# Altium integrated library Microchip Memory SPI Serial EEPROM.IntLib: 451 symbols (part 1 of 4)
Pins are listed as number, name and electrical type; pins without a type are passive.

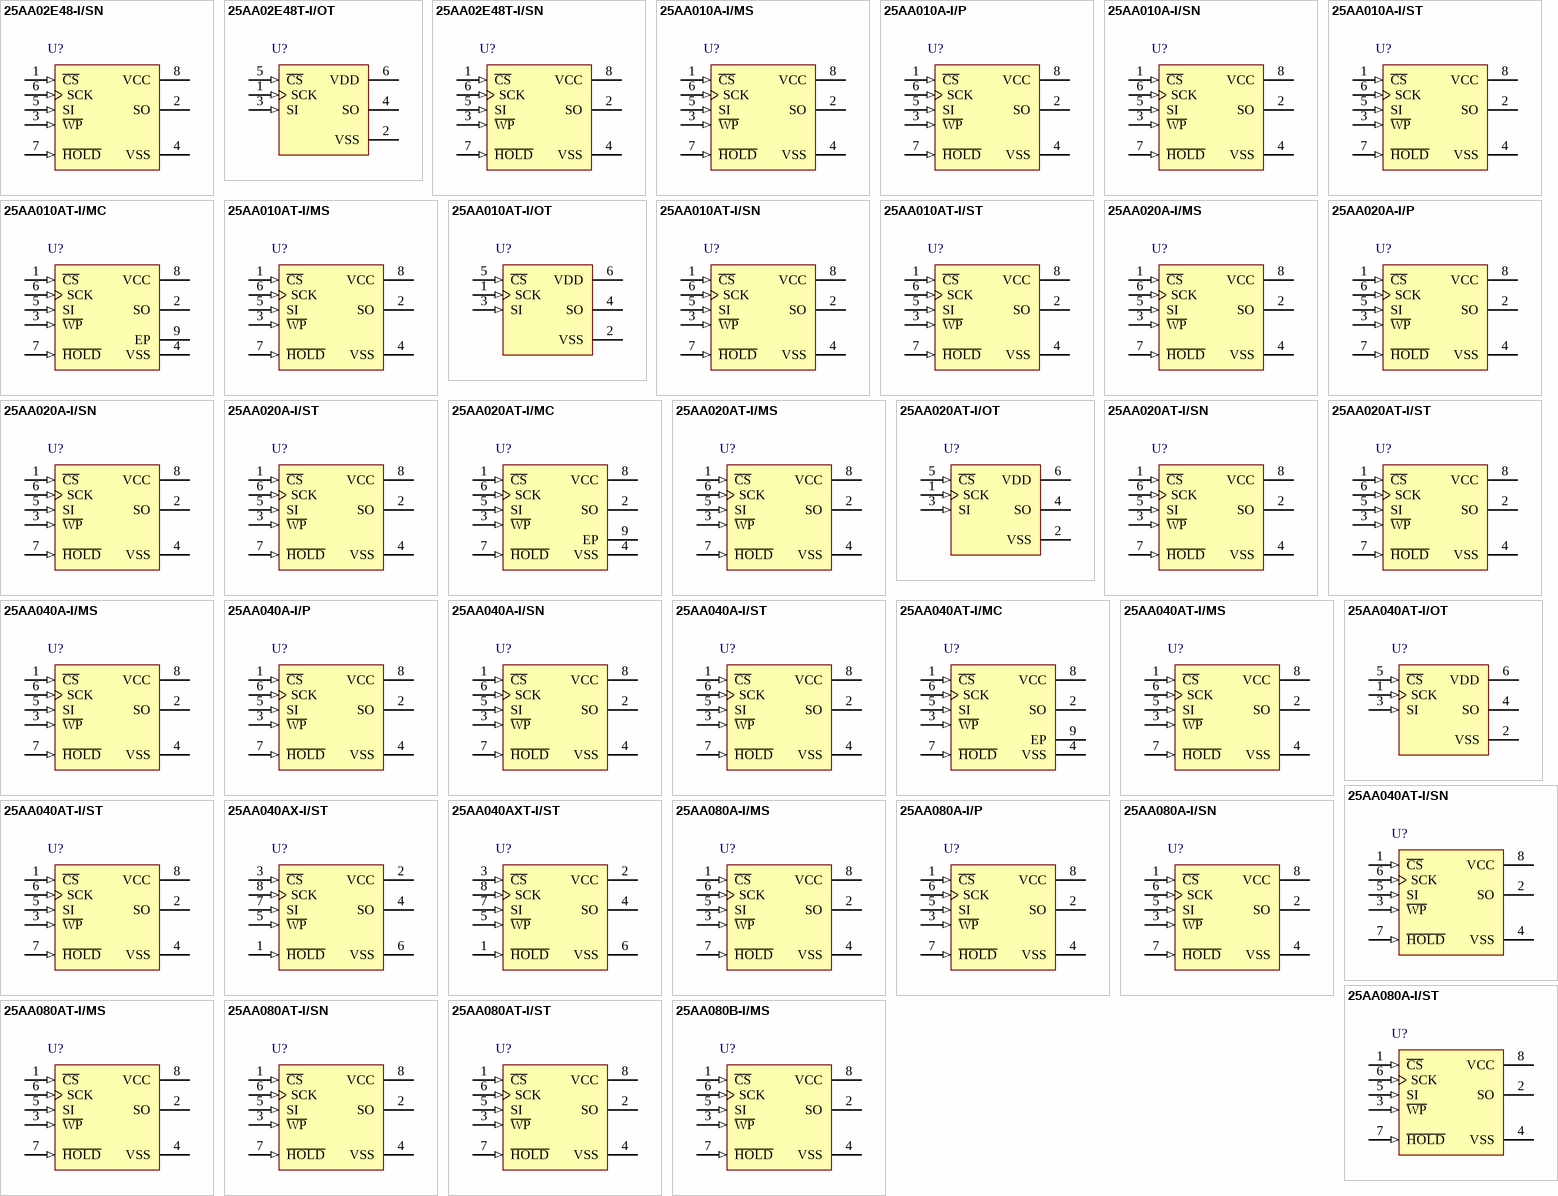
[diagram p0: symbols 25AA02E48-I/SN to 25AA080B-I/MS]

## 25AA02E48-I/SN
designator U?
2K SPI Bus Serial EEPROM with EUI-48 Node Identity, 8-Pin SOIC, Industrial Temperature
footprint SOIC-SN8_N (SOIC, 8-Leads, Body 4.9x3.8mm, Pitch 1.27mm, IPC Medium Density)
footprint SOIC-SN8_L (SOIC, 8-Leads, Body 4.9x3.8mm, Pitch 1.27mm, IPC High Density)
footprint SOIC-SN8_M (SOIC, 8-Leads, Body 4.9x3.8mm, Pitch 1.27mm, IPC Low Density)
pins: 1 ~{CS} (in), 2 SO (hiz), 3 ~{WP} (in), 4 VSS (power), 5 SI (in), 6 SCK (in), 7 ~{HOLD} (in), 8 VCC (power)

## 25AA02E48T-I/OT
designator U?
2K SPI Bus Serial EEPROM with EUI-48 Node Identity, 6-Pin SOT-23, Industrial Temperature, Tape and Reel
footprint SOT-23-OT6_N (SOT23, 6-Leads, Body 2.9x1.6mm, Pitch 0.95mm, Lead Span 2.7mm, IPC Medium Density)
footprint SOT-23-OT6_L (SOT23, 6-Leads, Body 2.9x1.6mm, Pitch 0.95mm, Lead Span 2.7mm, IPC High Density)
footprint SOT-23-OT6_M (SOT23, 6-Leads, Body 2.9x1.6mm, Pitch 0.95mm, Lead Span 2.7mm, IPC Low Density)
pins: 1 SCK (in), 2 VSS (power), 3 SI (in), 4 SO (hiz), 5 ~{CS} (in), 6 VDD (power)

## 25AA02E48T-I/SN
designator U?
2K SPI Bus Serial EEPROM with EUI-48 Node Identity, 8-Pin SOIC, Industrial Temperature, Tape and Reel
footprint SOIC-SN8_N (SOIC, 8-Leads, Body 4.9x3.8mm, Pitch 1.27mm, IPC Medium Density)
footprint SOIC-SN8_L (SOIC, 8-Leads, Body 4.9x3.8mm, Pitch 1.27mm, IPC High Density)
footprint SOIC-SN8_M (SOIC, 8-Leads, Body 4.9x3.8mm, Pitch 1.27mm, IPC Low Density)
pins: 1 ~{CS} (in), 2 SO (hiz), 3 ~{WP} (in), 4 VSS (power), 5 SI (in), 6 SCK (in), 7 ~{HOLD} (in), 8 VCC (power)

## 25AA010A-I/MS
designator U?
1K SPI Bus Serial EEPROM, 8-Pin MSOP, Industrial Temperature
footprint MSOP-MS8_N (TSOP, 8-Leads, Body 3x3mm, Pitch 0.65mm, IPC Medium Density)
footprint MSOP-MS8_L (TSOP, 8-Leads, Body 3x3mm, Pitch 0.65mm, IPC High Density)
footprint MSOP-MS8_M (TSOP, 8-Leads, Body 3x3mm, Pitch 0.65mm, IPC Low Density)
pins: 1 ~{CS} (in), 2 SO (hiz), 3 ~{WP} (in), 4 VSS (power), 5 SI (in), 6 SCK (in), 7 ~{HOLD} (in), 8 VCC (power)

## 25AA010A-I/P
designator U?
1K SPI Bus Serial EEPROM, 8-Pin PDIP, Industrial Temperature
footprint PDIP300-P8 (DIP, 8-Leads, Row Spacing 7.62mm, Pitch 2.54mm, Body 9.5x6.6mm)
pins: 1 ~{CS} (in), 2 SO (hiz), 3 ~{WP} (in), 4 VSS (power), 5 SI (in), 6 SCK (in), 7 ~{HOLD} (in), 8 VCC (power)

## 25AA010A-I/SN
designator U?
1K SPI Bus Serial EEPROM, 8-Pin SOIC, Industrial Temperature
footprint SOIC-SN8_N (SOIC, 8-Leads, Body 4.9x3.8mm, Pitch 1.27mm, IPC Medium Density)
footprint SOIC-SN8_L (SOIC, 8-Leads, Body 4.9x3.8mm, Pitch 1.27mm, IPC High Density)
footprint SOIC-SN8_M (SOIC, 8-Leads, Body 4.9x3.8mm, Pitch 1.27mm, IPC Low Density)
pins: 1 ~{CS} (in), 2 SO (hiz), 3 ~{WP} (in), 4 VSS (power), 5 SI (in), 6 SCK (in), 7 ~{HOLD} (in), 8 VCC (power)

## 25AA010A-I/ST
designator U?
1K SPI Bus Serial EEPROM, 8-Pin TSSOP, Industrial Temperature
footprint TSSOP-ST8_N (TSOP, 8-Leads, Body 3x4.4mm, Pitch 0.65mm, IPC Medium Density)
footprint TSSOP-ST8_L (TSOP, 8-Leads, Body 3x4.4mm, Pitch 0.65mm, IPC High Density)
footprint TSSOP-ST8_M (TSOP, 8-Leads, Body 3x4.4mm, Pitch 0.65mm, IPC Low Density)
pins: 1 ~{CS} (in), 2 SO (hiz), 3 ~{WP} (in), 4 VSS (power), 5 SI (in), 6 SCK (in), 7 ~{HOLD} (in), 8 VCC (power)

## 25AA010AT-I/MC
designator U?
1K SPI Bus Serial EEPROM, 8-Pin DFN, Industrial Temperature, Tape and Reel
footprint DFN-MC8 (SON, 8-Leads, Body 2x3mm, Pitch 0.5mm, Microchip Recommended)
pins: 1 ~{CS} (in), 2 SO (hiz), 3 ~{WP} (in), 4 VSS (power), 5 SI (in), 6 SCK (in), 7 ~{HOLD} (in), 8 VCC (power), 9 EP

## 25AA010AT-I/MS
designator U?
1K SPI Bus Serial EEPROM, 8-Pin MSOP, Industrial Temperature, Tape and Reel
footprint MSOP-MS8_N (TSOP, 8-Leads, Body 3x3mm, Pitch 0.65mm, IPC Medium Density)
footprint MSOP-MS8_L (TSOP, 8-Leads, Body 3x3mm, Pitch 0.65mm, IPC High Density)
footprint MSOP-MS8_M (TSOP, 8-Leads, Body 3x3mm, Pitch 0.65mm, IPC Low Density)
pins: 1 ~{CS} (in), 2 SO (hiz), 3 ~{WP} (in), 4 VSS (power), 5 SI (in), 6 SCK (in), 7 ~{HOLD} (in), 8 VCC (power)

## 25AA010AT-I/OT
designator U?
1K SPI Bus Serial EEPROM, 6-Pin SOT-23, Industrial Temperature, Tape and Reel
footprint SOT-23-OT6_N (SOT23, 6-Leads, Body 2.9x1.6mm, Pitch 0.95mm, Lead Span 2.7mm, IPC Medium Density)
footprint SOT-23-OT6_L (SOT23, 6-Leads, Body 2.9x1.6mm, Pitch 0.95mm, Lead Span 2.7mm, IPC High Density)
footprint SOT-23-OT6_M (SOT23, 6-Leads, Body 2.9x1.6mm, Pitch 0.95mm, Lead Span 2.7mm, IPC Low Density)
pins: 1 SCK (in), 2 VSS (power), 3 SI (in), 4 SO (hiz), 5 ~{CS} (in), 6 VDD (power)

## 25AA010AT-I/SN
designator U?
1K SPI Bus Serial EEPROM, 8-Pin SOIC, Industrial Temperature, Tape and Reel
footprint SOIC-SN8_N (SOIC, 8-Leads, Body 4.9x3.8mm, Pitch 1.27mm, IPC Medium Density)
footprint SOIC-SN8_L (SOIC, 8-Leads, Body 4.9x3.8mm, Pitch 1.27mm, IPC High Density)
footprint SOIC-SN8_M (SOIC, 8-Leads, Body 4.9x3.8mm, Pitch 1.27mm, IPC Low Density)
pins: 1 ~{CS} (in), 2 SO (hiz), 3 ~{WP} (in), 4 VSS (power), 5 SI (in), 6 SCK (in), 7 ~{HOLD} (in), 8 VCC (power)

## 25AA010AT-I/ST
designator U?
1K SPI Bus Serial EEPROM, 8-Pin TSSOP, Industrial Temperature, Tape and Reel
footprint TSSOP-ST8_N (TSOP, 8-Leads, Body 3x4.4mm, Pitch 0.65mm, IPC Medium Density)
footprint TSSOP-ST8_L (TSOP, 8-Leads, Body 3x4.4mm, Pitch 0.65mm, IPC High Density)
footprint TSSOP-ST8_M (TSOP, 8-Leads, Body 3x4.4mm, Pitch 0.65mm, IPC Low Density)
pins: 1 ~{CS} (in), 2 SO (hiz), 3 ~{WP} (in), 4 VSS (power), 5 SI (in), 6 SCK (in), 7 ~{HOLD} (in), 8 VCC (power)

## 25AA020A-I/MS
designator U?
2K SPI Bus Serial EEPROM, 8-Pin MSOP, Industrial Temperature
footprint MSOP-MS8_N (TSOP, 8-Leads, Body 3x3mm, Pitch 0.65mm, IPC Medium Density)
footprint MSOP-MS8_L (TSOP, 8-Leads, Body 3x3mm, Pitch 0.65mm, IPC High Density)
footprint MSOP-MS8_M (TSOP, 8-Leads, Body 3x3mm, Pitch 0.65mm, IPC Low Density)
pins: 1 ~{CS} (in), 2 SO (hiz), 3 ~{WP} (in), 4 VSS (power), 5 SI (in), 6 SCK (in), 7 ~{HOLD} (in), 8 VCC (power)

## 25AA020A-I/P
designator U?
2K SPI Bus Serial EEPROM, 8-Pin PDIP, Industrial Temperature
footprint PDIP300-P8 (DIP, 8-Leads, Row Spacing 7.62mm, Pitch 2.54mm, Body 9.5x6.6mm)
pins: 1 ~{CS} (in), 2 SO (hiz), 3 ~{WP} (in), 4 VSS (power), 5 SI (in), 6 SCK (in), 7 ~{HOLD} (in), 8 VCC (power)

## 25AA020A-I/SN
designator U?
2K SPI Bus Serial EEPROM, 8-Pin SOIC, Industrial Temperature
footprint SOIC-SN8_N (SOIC, 8-Leads, Body 4.9x3.8mm, Pitch 1.27mm, IPC Medium Density)
footprint SOIC-SN8_L (SOIC, 8-Leads, Body 4.9x3.8mm, Pitch 1.27mm, IPC High Density)
footprint SOIC-SN8_M (SOIC, 8-Leads, Body 4.9x3.8mm, Pitch 1.27mm, IPC Low Density)
pins: 1 ~{CS} (in), 2 SO (hiz), 3 ~{WP} (in), 4 VSS (power), 5 SI (in), 6 SCK (in), 7 ~{HOLD} (in), 8 VCC (power)

## 25AA020A-I/ST
designator U?
2K SPI Bus Serial EEPROM, 8-Pin TSSOP, Industrial Temperature
footprint TSSOP-ST8_N (TSOP, 8-Leads, Body 3x4.4mm, Pitch 0.65mm, IPC Medium Density)
footprint TSSOP-ST8_L (TSOP, 8-Leads, Body 3x4.4mm, Pitch 0.65mm, IPC High Density)
footprint TSSOP-ST8_M (TSOP, 8-Leads, Body 3x4.4mm, Pitch 0.65mm, IPC Low Density)
pins: 1 ~{CS} (in), 2 SO (hiz), 3 ~{WP} (in), 4 VSS (power), 5 SI (in), 6 SCK (in), 7 ~{HOLD} (in), 8 VCC (power)

## 25AA020AT-I/MC
designator U?
2K SPI Bus Serial EEPROM, 8-Pin DFN, Industrial Temperature, Tape and Reel
footprint DFN-MC8 (SON, 8-Leads, Body 2x3mm, Pitch 0.5mm, Microchip Recommended)
pins: 1 ~{CS} (in), 2 SO (hiz), 3 ~{WP} (in), 4 VSS (power), 5 SI (in), 6 SCK (in), 7 ~{HOLD} (in), 8 VCC (power), 9 EP

## 25AA020AT-I/MS
designator U?
2K SPI Bus Serial EEPROM, 8-Pin MSOP, Industrial Temperature, Tape and Reel
footprint MSOP-MS8_N (TSOP, 8-Leads, Body 3x3mm, Pitch 0.65mm, IPC Medium Density)
footprint MSOP-MS8_L (TSOP, 8-Leads, Body 3x3mm, Pitch 0.65mm, IPC High Density)
footprint MSOP-MS8_M (TSOP, 8-Leads, Body 3x3mm, Pitch 0.65mm, IPC Low Density)
pins: 1 ~{CS} (in), 2 SO (hiz), 3 ~{WP} (in), 4 VSS (power), 5 SI (in), 6 SCK (in), 7 ~{HOLD} (in), 8 VCC (power)

## 25AA020AT-I/OT
designator U?
2K SPI Bus Serial EEPROM, 6-Pin SOT-23, Industrial Temperature, Tape and Reel
footprint SOT-23-OT6_N (SOT23, 6-Leads, Body 2.9x1.6mm, Pitch 0.95mm, Lead Span 2.7mm, IPC Medium Density)
footprint SOT-23-OT6_L (SOT23, 6-Leads, Body 2.9x1.6mm, Pitch 0.95mm, Lead Span 2.7mm, IPC High Density)
footprint SOT-23-OT6_M (SOT23, 6-Leads, Body 2.9x1.6mm, Pitch 0.95mm, Lead Span 2.7mm, IPC Low Density)
pins: 1 SCK (in), 2 VSS (power), 3 SI (in), 4 SO (hiz), 5 ~{CS} (in), 6 VDD (power)

## 25AA020AT-I/SN
designator U?
2K SPI Bus Serial EEPROM, 8-Pin SOIC, Industrial Temperature, Tape and Reel
footprint SOIC-SN8_N (SOIC, 8-Leads, Body 4.9x3.8mm, Pitch 1.27mm, IPC Medium Density)
footprint SOIC-SN8_L (SOIC, 8-Leads, Body 4.9x3.8mm, Pitch 1.27mm, IPC High Density)
footprint SOIC-SN8_M (SOIC, 8-Leads, Body 4.9x3.8mm, Pitch 1.27mm, IPC Low Density)
pins: 1 ~{CS} (in), 2 SO (hiz), 3 ~{WP} (in), 4 VSS (power), 5 SI (in), 6 SCK (in), 7 ~{HOLD} (in), 8 VCC (power)

## 25AA020AT-I/ST
designator U?
2K SPI Bus Serial EEPROM, 8-Pin TSSOP, Industrial Temperature, Tape and Reel
footprint TSSOP-ST8_N (TSOP, 8-Leads, Body 3x4.4mm, Pitch 0.65mm, IPC Medium Density)
footprint TSSOP-ST8_L (TSOP, 8-Leads, Body 3x4.4mm, Pitch 0.65mm, IPC High Density)
footprint TSSOP-ST8_M (TSOP, 8-Leads, Body 3x4.4mm, Pitch 0.65mm, IPC Low Density)
pins: 1 ~{CS} (in), 2 SO (hiz), 3 ~{WP} (in), 4 VSS (power), 5 SI (in), 6 SCK (in), 7 ~{HOLD} (in), 8 VCC (power)

## 25AA040A-I/MS
designator U?
4K SPI Bus Serial EEPROM, 8-Pin MSOP, Industrial Temperature
footprint MSOP-MS8_N (TSOP, 8-Leads, Body 3x3mm, Pitch 0.65mm, IPC Medium Density)
footprint MSOP-MS8_L (TSOP, 8-Leads, Body 3x3mm, Pitch 0.65mm, IPC High Density)
footprint MSOP-MS8_M (TSOP, 8-Leads, Body 3x3mm, Pitch 0.65mm, IPC Low Density)
pins: 1 ~{CS} (in), 2 SO (hiz), 3 ~{WP} (in), 4 VSS (power), 5 SI (in), 6 SCK (in), 7 ~{HOLD} (in), 8 VCC (power)

## 25AA040A-I/P
designator U?
4K SPI Bus Serial EEPROM, 8-Pin PDIP, Industrial Temperature
footprint PDIP300-P8 (DIP, 8-Leads, Row Spacing 7.62mm, Pitch 2.54mm, Body 9.5x6.6mm)
pins: 1 ~{CS} (in), 2 SO (hiz), 3 ~{WP} (in), 4 VSS (power), 5 SI (in), 6 SCK (in), 7 ~{HOLD} (in), 8 VCC (power)

## 25AA040A-I/SN
designator U?
4K SPI Bus Serial EEPROM, 8-Pin SOIC, Industrial Temperature
footprint SOIC-SN8_N (SOIC, 8-Leads, Body 4.9x3.8mm, Pitch 1.27mm, IPC Medium Density)
footprint SOIC-SN8_L (SOIC, 8-Leads, Body 4.9x3.8mm, Pitch 1.27mm, IPC High Density)
footprint SOIC-SN8_M (SOIC, 8-Leads, Body 4.9x3.8mm, Pitch 1.27mm, IPC Low Density)
pins: 1 ~{CS} (in), 2 SO (hiz), 3 ~{WP} (in), 4 VSS (power), 5 SI (in), 6 SCK (in), 7 ~{HOLD} (in), 8 VCC (power)

## 25AA040A-I/ST
designator U?
4K SPI Bus Serial EEPROM, 8-Pin TSSOP, Industrial Temperature
footprint TSSOP-ST8_N (TSOP, 8-Leads, Body 3x4.4mm, Pitch 0.65mm, IPC Medium Density)
footprint TSSOP-ST8_L (TSOP, 8-Leads, Body 3x4.4mm, Pitch 0.65mm, IPC High Density)
footprint TSSOP-ST8_M (TSOP, 8-Leads, Body 3x4.4mm, Pitch 0.65mm, IPC Low Density)
pins: 1 ~{CS} (in), 2 SO (hiz), 3 ~{WP} (in), 4 VSS (power), 5 SI (in), 6 SCK (in), 7 ~{HOLD} (in), 8 VCC (power)

## 25AA040AT-I/MC
designator U?
4K SPI Bus Serial EEPROM, 8-Pin DFN, Industrial Temperature, Tape and Reel
footprint DFN-MC8 (SON, 8-Leads, Body 2x3mm, Pitch 0.5mm, Microchip Recommended)
pins: 1 ~{CS} (in), 2 SO (hiz), 3 ~{WP} (in), 4 VSS (power), 5 SI (in), 6 SCK (in), 7 ~{HOLD} (in), 8 VCC (power), 9 EP

## 25AA040AT-I/MS
designator U?
4K SPI Bus Serial EEPROM, 8-Pin MSOP, Industrial Temperature, Tape and Reel
footprint MSOP-MS8_N (TSOP, 8-Leads, Body 3x3mm, Pitch 0.65mm, IPC Medium Density)
footprint MSOP-MS8_L (TSOP, 8-Leads, Body 3x3mm, Pitch 0.65mm, IPC High Density)
footprint MSOP-MS8_M (TSOP, 8-Leads, Body 3x3mm, Pitch 0.65mm, IPC Low Density)
pins: 1 ~{CS} (in), 2 SO (hiz), 3 ~{WP} (in), 4 VSS (power), 5 SI (in), 6 SCK (in), 7 ~{HOLD} (in), 8 VCC (power)

## 25AA040AT-I/OT
designator U?
4K SPI Bus Serial EEPROM, 6-Pin SOT-23, Industrial Temperature, Tape and Reel
footprint SOT-23-OT6_N (SOT23, 6-Leads, Body 2.9x1.6mm, Pitch 0.95mm, Lead Span 2.7mm, IPC Medium Density)
footprint SOT-23-OT6_L (SOT23, 6-Leads, Body 2.9x1.6mm, Pitch 0.95mm, Lead Span 2.7mm, IPC High Density)
footprint SOT-23-OT6_M (SOT23, 6-Leads, Body 2.9x1.6mm, Pitch 0.95mm, Lead Span 2.7mm, IPC Low Density)
pins: 1 SCK (in), 2 VSS (power), 3 SI (in), 4 SO (hiz), 5 ~{CS} (in), 6 VDD (power)

## 25AA040AT-I/SN
designator U?
4K SPI Bus Serial EEPROM, 8-Pin SOIC, Industrial Temperature, Tape and Reel
footprint SOIC-SN8_N (SOIC, 8-Leads, Body 4.9x3.8mm, Pitch 1.27mm, IPC Medium Density)
footprint SOIC-SN8_L (SOIC, 8-Leads, Body 4.9x3.8mm, Pitch 1.27mm, IPC High Density)
footprint SOIC-SN8_M (SOIC, 8-Leads, Body 4.9x3.8mm, Pitch 1.27mm, IPC Low Density)
pins: 1 ~{CS} (in), 2 SO (hiz), 3 ~{WP} (in), 4 VSS (power), 5 SI (in), 6 SCK (in), 7 ~{HOLD} (in), 8 VCC (power)

## 25AA040AT-I/ST
designator U?
4K SPI Bus Serial EEPROM, 8-Pin TSSOP, Industrial Temperature, Tape and Reel
footprint TSSOP-ST8_N (TSOP, 8-Leads, Body 3x4.4mm, Pitch 0.65mm, IPC Medium Density)
footprint TSSOP-ST8_L (TSOP, 8-Leads, Body 3x4.4mm, Pitch 0.65mm, IPC High Density)
footprint TSSOP-ST8_M (TSOP, 8-Leads, Body 3x4.4mm, Pitch 0.65mm, IPC Low Density)
pins: 1 ~{CS} (in), 2 SO (hiz), 3 ~{WP} (in), 4 VSS (power), 5 SI (in), 6 SCK (in), 7 ~{HOLD} (in), 8 VCC (power)

## 25AA040AX-I/ST
designator U?
4K SPI Bus Serial EEPROM, 8-Pin TSSOP, Industrial Temperature
footprint TSSOP-ST8_N (TSOP, 8-Leads, Body 3x4.4mm, Pitch 0.65mm, IPC Medium Density)
footprint TSSOP-ST8_L (TSOP, 8-Leads, Body 3x4.4mm, Pitch 0.65mm, IPC High Density)
footprint TSSOP-ST8_M (TSOP, 8-Leads, Body 3x4.4mm, Pitch 0.65mm, IPC Low Density)
pins: 1 ~{HOLD} (in), 2 VCC (power), 3 ~{CS} (in), 4 SO (hiz), 5 ~{WP} (in), 6 VSS (power), 7 SI (in), 8 SCK (in)

## 25AA040AXT-I/ST
designator U?
4K SPI Bus Serial EEPROM, 8-Pin TSSOP, Industrial Temperature, Tape and Reel
footprint TSSOP-ST8_N (TSOP, 8-Leads, Body 3x4.4mm, Pitch 0.65mm, IPC Medium Density)
footprint TSSOP-ST8_L (TSOP, 8-Leads, Body 3x4.4mm, Pitch 0.65mm, IPC High Density)
footprint TSSOP-ST8_M (TSOP, 8-Leads, Body 3x4.4mm, Pitch 0.65mm, IPC Low Density)
pins: 1 ~{HOLD} (in), 2 VCC (power), 3 ~{CS} (in), 4 SO (hiz), 5 ~{WP} (in), 6 VSS (power), 7 SI (in), 8 SCK (in)

## 25AA080A-I/MS
designator U?
8K SPI Bus Serial EEPROM, 8-Pin MSOP, Industrial Temperature; ComponentAvailability: Unknown. Contact manufacturer to determine status.
footprint MSOP-MS8_N (TSOP, 8-Leads, Body 3x3mm, Pitch 0.65mm, IPC Medium Density)
footprint MSOP-MS8_L (TSOP, 8-Leads, Body 3x3mm, Pitch 0.65mm, IPC High Density)
footprint MSOP-MS8_M (TSOP, 8-Leads, Body 3x3mm, Pitch 0.65mm, IPC Low Density)
pins: 1 ~{CS} (in), 2 SO (hiz), 3 ~{WP} (in), 4 VSS (power), 5 SI (in), 6 SCK (in), 7 ~{HOLD} (in), 8 VCC (power)

## 25AA080A-I/P
designator U?
8K SPI Bus Serial EEPROM, 8-Pin PDIP, Industrial Temperature; ComponentAvailability: Unknown. Contact manufacturer to determine status.
footprint PDIP300-P8 (DIP, 8-Leads, Row Spacing 7.62mm, Pitch 2.54mm, Body 9.5x6.6mm)
pins: 1 ~{CS} (in), 2 SO (hiz), 3 ~{WP} (in), 4 VSS (power), 5 SI (in), 6 SCK (in), 7 ~{HOLD} (in), 8 VCC (power)

## 25AA080A-I/SN
designator U?
8K SPI Bus Serial EEPROM, 8-Pin SOIC, Industrial Temperature; ComponentAvailability: Unknown. Contact manufacturer to determine status.
footprint SOIC-SN8_N (SOIC, 8-Leads, Body 4.9x3.8mm, Pitch 1.27mm, IPC Medium Density)
footprint SOIC-SN8_L (SOIC, 8-Leads, Body 4.9x3.8mm, Pitch 1.27mm, IPC High Density)
footprint SOIC-SN8_M (SOIC, 8-Leads, Body 4.9x3.8mm, Pitch 1.27mm, IPC Low Density)
pins: 1 ~{CS} (in), 2 SO (hiz), 3 ~{WP} (in), 4 VSS (power), 5 SI (in), 6 SCK (in), 7 ~{HOLD} (in), 8 VCC (power)

## 25AA080A-I/ST
designator U?
8K SPI Bus Serial EEPROM, 8-Pin TSSOP, Industrial Temperature; ComponentAvailability: Unknown. Contact manufacturer to determine status.
footprint TSSOP-ST8_N (TSOP, 8-Leads, Body 3x4.4mm, Pitch 0.65mm, IPC Medium Density)
footprint TSSOP-ST8_L (TSOP, 8-Leads, Body 3x4.4mm, Pitch 0.65mm, IPC High Density)
footprint TSSOP-ST8_M (TSOP, 8-Leads, Body 3x4.4mm, Pitch 0.65mm, IPC Low Density)
pins: 1 ~{CS} (in), 2 SO (hiz), 3 ~{WP} (in), 4 VSS (power), 5 SI (in), 6 SCK (in), 7 ~{HOLD} (in), 8 VCC (power)

## 25AA080AT-I/MS
designator U?
8K SPI Bus Serial EEPROM, 8-Pin MSOP, Industrial Temperature, Tape and Reel; ComponentAvailability: Unknown. Contact manufacturer to determine status.
footprint MSOP-MS8_N (TSOP, 8-Leads, Body 3x3mm, Pitch 0.65mm, IPC Medium Density)
footprint MSOP-MS8_L (TSOP, 8-Leads, Body 3x3mm, Pitch 0.65mm, IPC High Density)
footprint MSOP-MS8_M (TSOP, 8-Leads, Body 3x3mm, Pitch 0.65mm, IPC Low Density)
pins: 1 ~{CS} (in), 2 SO (hiz), 3 ~{WP} (in), 4 VSS (power), 5 SI (in), 6 SCK (in), 7 ~{HOLD} (in), 8 VCC (power)

## 25AA080AT-I/SN
designator U?
8K SPI Bus Serial EEPROM, 8-Pin SOIC, Industrial Temperature, Tape and Reel; ComponentAvailability: Unknown. Contact manufacturer to determine status.
footprint SOIC-SN8_N (SOIC, 8-Leads, Body 4.9x3.8mm, Pitch 1.27mm, IPC Medium Density)
footprint SOIC-SN8_L (SOIC, 8-Leads, Body 4.9x3.8mm, Pitch 1.27mm, IPC High Density)
footprint SOIC-SN8_M (SOIC, 8-Leads, Body 4.9x3.8mm, Pitch 1.27mm, IPC Low Density)
pins: 1 ~{CS} (in), 2 SO (hiz), 3 ~{WP} (in), 4 VSS (power), 5 SI (in), 6 SCK (in), 7 ~{HOLD} (in), 8 VCC (power)

## 25AA080AT-I/ST
designator U?
8K SPI Bus Serial EEPROM, 8-Pin TSSOP, Industrial Temperature, Tape and Reel; ComponentAvailability: Unknown. Contact manufacturer to determine status.
footprint TSSOP-ST8_N (TSOP, 8-Leads, Body 3x4.4mm, Pitch 0.65mm, IPC Medium Density)
footprint TSSOP-ST8_L (TSOP, 8-Leads, Body 3x4.4mm, Pitch 0.65mm, IPC High Density)
footprint TSSOP-ST8_M (TSOP, 8-Leads, Body 3x4.4mm, Pitch 0.65mm, IPC Low Density)
pins: 1 ~{CS} (in), 2 SO (hiz), 3 ~{WP} (in), 4 VSS (power), 5 SI (in), 6 SCK (in), 7 ~{HOLD} (in), 8 VCC (power)

## 25AA080B-I/MS
designator U?
8K SPI Bus Serial EEPROM, 8-Pin MSOP, Industrial Temperature; ComponentAvailability: Unknown. Contact manufacturer to determine status.
footprint MSOP-MS8_N (TSOP, 8-Leads, Body 3x3mm, Pitch 0.65mm, IPC Medium Density)
footprint MSOP-MS8_L (TSOP, 8-Leads, Body 3x3mm, Pitch 0.65mm, IPC High Density)
footprint MSOP-MS8_M (TSOP, 8-Leads, Body 3x3mm, Pitch 0.65mm, IPC Low Density)
pins: 1 ~{CS} (in), 2 SO (hiz), 3 ~{WP} (in), 4 VSS (power), 5 SI (in), 6 SCK (in), 7 ~{HOLD} (in), 8 VCC (power)

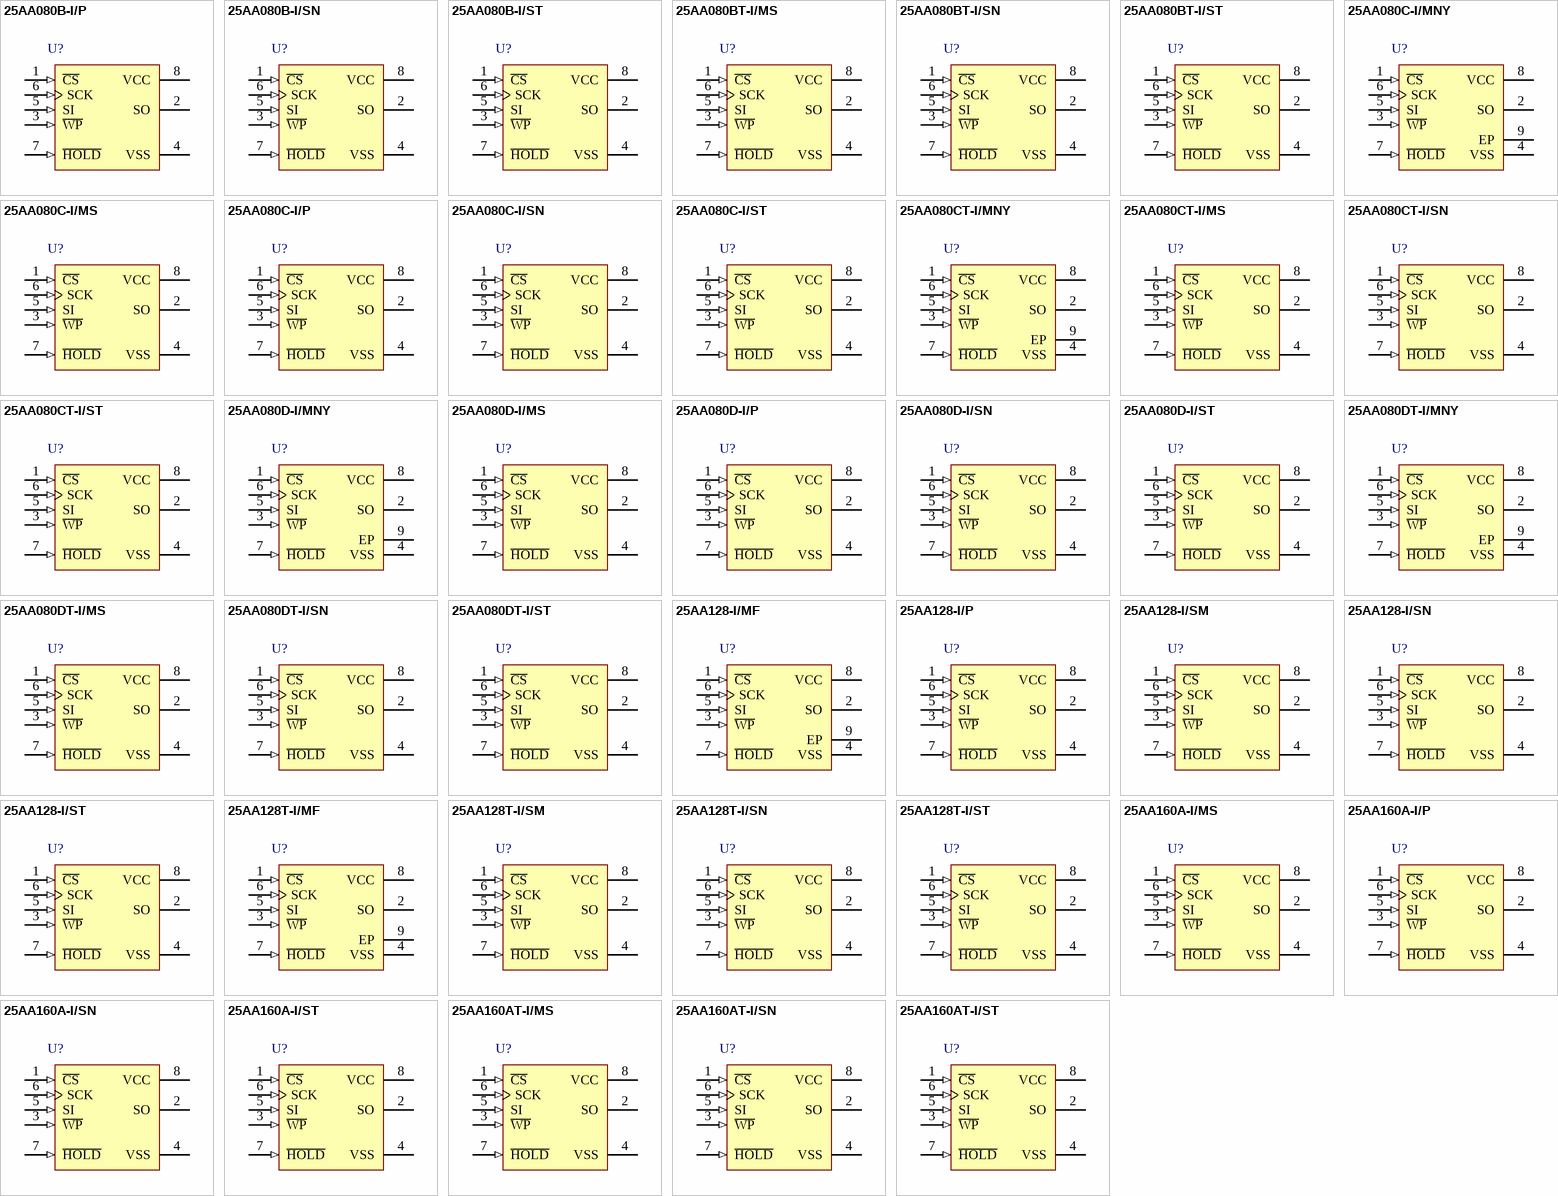
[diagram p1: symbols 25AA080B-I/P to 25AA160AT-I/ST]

## 25AA080B-I/P
designator U?
8K SPI Bus Serial EEPROM, 8-Pin PDIP, Industrial Temperature; ComponentAvailability: Unknown. Contact manufacturer to determine status.
footprint PDIP300-P8 (DIP, 8-Leads, Row Spacing 7.62mm, Pitch 2.54mm, Body 9.5x6.6mm)
pins: 1 ~{CS} (in), 2 SO (hiz), 3 ~{WP} (in), 4 VSS (power), 5 SI (in), 6 SCK (in), 7 ~{HOLD} (in), 8 VCC (power)

## 25AA080B-I/SN
designator U?
8K SPI Bus Serial EEPROM, 8-Pin SOIC, Industrial Temperature; ComponentAvailability: Unknown. Contact manufacturer to determine status.
footprint SOIC-SN8_N (SOIC, 8-Leads, Body 4.9x3.8mm, Pitch 1.27mm, IPC Medium Density)
footprint SOIC-SN8_L (SOIC, 8-Leads, Body 4.9x3.8mm, Pitch 1.27mm, IPC High Density)
footprint SOIC-SN8_M (SOIC, 8-Leads, Body 4.9x3.8mm, Pitch 1.27mm, IPC Low Density)
pins: 1 ~{CS} (in), 2 SO (hiz), 3 ~{WP} (in), 4 VSS (power), 5 SI (in), 6 SCK (in), 7 ~{HOLD} (in), 8 VCC (power)

## 25AA080B-I/ST
designator U?
8K SPI Bus Serial EEPROM, 8-Pin TSSOP, Industrial Temperature; ComponentAvailability: Unknown. Contact manufacturer to determine status.
footprint TSSOP-ST8_N (TSOP, 8-Leads, Body 3x4.4mm, Pitch 0.65mm, IPC Medium Density)
footprint TSSOP-ST8_L (TSOP, 8-Leads, Body 3x4.4mm, Pitch 0.65mm, IPC High Density)
footprint TSSOP-ST8_M (TSOP, 8-Leads, Body 3x4.4mm, Pitch 0.65mm, IPC Low Density)
pins: 1 ~{CS} (in), 2 SO (hiz), 3 ~{WP} (in), 4 VSS (power), 5 SI (in), 6 SCK (in), 7 ~{HOLD} (in), 8 VCC (power)

## 25AA080BT-I/MS
designator U?
8K SPI Bus Serial EEPROM, 8-Pin MSOP, Industrial Temperature, Tape and Reel; ComponentAvailability: Unknown. Contact manufacturer to determine status.
footprint MSOP-MS8_N (TSOP, 8-Leads, Body 3x3mm, Pitch 0.65mm, IPC Medium Density)
footprint MSOP-MS8_L (TSOP, 8-Leads, Body 3x3mm, Pitch 0.65mm, IPC High Density)
footprint MSOP-MS8_M (TSOP, 8-Leads, Body 3x3mm, Pitch 0.65mm, IPC Low Density)
pins: 1 ~{CS} (in), 2 SO (hiz), 3 ~{WP} (in), 4 VSS (power), 5 SI (in), 6 SCK (in), 7 ~{HOLD} (in), 8 VCC (power)

## 25AA080BT-I/SN
designator U?
8K SPI Bus Serial EEPROM, 8-Pin SOIC, Industrial Temperature, Tape and Reel; ComponentAvailability: Unknown. Contact manufacturer to determine status.
footprint SOIC-SN8_N (SOIC, 8-Leads, Body 4.9x3.8mm, Pitch 1.27mm, IPC Medium Density)
footprint SOIC-SN8_L (SOIC, 8-Leads, Body 4.9x3.8mm, Pitch 1.27mm, IPC High Density)
footprint SOIC-SN8_M (SOIC, 8-Leads, Body 4.9x3.8mm, Pitch 1.27mm, IPC Low Density)
pins: 1 ~{CS} (in), 2 SO (hiz), 3 ~{WP} (in), 4 VSS (power), 5 SI (in), 6 SCK (in), 7 ~{HOLD} (in), 8 VCC (power)

## 25AA080BT-I/ST
designator U?
8K SPI Bus Serial EEPROM, 8-Pin TSSOP, Industrial Temperature, Tape and Reel; ComponentAvailability: Unknown. Contact manufacturer to determine status.
footprint TSSOP-ST8_N (TSOP, 8-Leads, Body 3x4.4mm, Pitch 0.65mm, IPC Medium Density)
footprint TSSOP-ST8_L (TSOP, 8-Leads, Body 3x4.4mm, Pitch 0.65mm, IPC High Density)
footprint TSSOP-ST8_M (TSOP, 8-Leads, Body 3x4.4mm, Pitch 0.65mm, IPC Low Density)
pins: 1 ~{CS} (in), 2 SO (hiz), 3 ~{WP} (in), 4 VSS (power), 5 SI (in), 6 SCK (in), 7 ~{HOLD} (in), 8 VCC (power)

## 25AA080C-I/MNY
designator U?
8K SPI Bus Serial EEPROM, 8-Pin TDFN, Industrial Temperature
footprint TDFN-MN8 (SON, 8-Leads, Body 2x3mm, Pitch 0.5mm, Microchip Recommended)
pins: 1 ~{CS} (in), 2 SO (hiz), 3 ~{WP} (in), 4 VSS (power), 5 SI (in), 6 SCK (in), 7 ~{HOLD} (in), 8 VCC (power), 9 EP

## 25AA080C-I/MS
designator U?
8K SPI Bus Serial EEPROM, 8-Pin MSOP, Industrial Temperature
footprint MSOP-MS8_N (TSOP, 8-Leads, Body 3x3mm, Pitch 0.65mm, IPC Medium Density)
footprint MSOP-MS8_L (TSOP, 8-Leads, Body 3x3mm, Pitch 0.65mm, IPC High Density)
footprint MSOP-MS8_M (TSOP, 8-Leads, Body 3x3mm, Pitch 0.65mm, IPC Low Density)
pins: 1 ~{CS} (in), 2 SO (hiz), 3 ~{WP} (in), 4 VSS (power), 5 SI (in), 6 SCK (in), 7 ~{HOLD} (in), 8 VCC (power)

## 25AA080C-I/P
designator U?
8K SPI Bus Serial EEPROM, 8-Pin PDIP, Industrial Temperature
footprint PDIP300-P8 (DIP, 8-Leads, Row Spacing 7.62mm, Pitch 2.54mm, Body 9.5x6.6mm)
pins: 1 ~{CS} (in), 2 SO (hiz), 3 ~{WP} (in), 4 VSS (power), 5 SI (in), 6 SCK (in), 7 ~{HOLD} (in), 8 VCC (power)

## 25AA080C-I/SN
designator U?
8K SPI Bus Serial EEPROM, 8-Pin SOIC, Industrial Temperature
footprint SOIC-SN8_N (SOIC, 8-Leads, Body 4.9x3.8mm, Pitch 1.27mm, IPC Medium Density)
footprint SOIC-SN8_L (SOIC, 8-Leads, Body 4.9x3.8mm, Pitch 1.27mm, IPC High Density)
footprint SOIC-SN8_M (SOIC, 8-Leads, Body 4.9x3.8mm, Pitch 1.27mm, IPC Low Density)
pins: 1 ~{CS} (in), 2 SO (hiz), 3 ~{WP} (in), 4 VSS (power), 5 SI (in), 6 SCK (in), 7 ~{HOLD} (in), 8 VCC (power)

## 25AA080C-I/ST
designator U?
8K SPI Bus Serial EEPROM, 8-Pin TSSOP, Industrial Temperature
footprint TSSOP-ST8_N (TSOP, 8-Leads, Body 3x4.4mm, Pitch 0.65mm, IPC Medium Density)
footprint TSSOP-ST8_L (TSOP, 8-Leads, Body 3x4.4mm, Pitch 0.65mm, IPC High Density)
footprint TSSOP-ST8_M (TSOP, 8-Leads, Body 3x4.4mm, Pitch 0.65mm, IPC Low Density)
pins: 1 ~{CS} (in), 2 SO (hiz), 3 ~{WP} (in), 4 VSS (power), 5 SI (in), 6 SCK (in), 7 ~{HOLD} (in), 8 VCC (power)

## 25AA080CT-I/MNY
designator U?
8K SPI Bus Serial EEPROM, 8-Pin TDFN, Industrial Temperature, Tape and Reel
footprint TDFN-MN8 (SON, 8-Leads, Body 2x3mm, Pitch 0.5mm, Microchip Recommended)
pins: 1 ~{CS} (in), 2 SO (hiz), 3 ~{WP} (in), 4 VSS (power), 5 SI (in), 6 SCK (in), 7 ~{HOLD} (in), 8 VCC (power), 9 EP

## 25AA080CT-I/MS
designator U?
8K SPI Bus Serial EEPROM, 8-Pin MSOP, Industrial Temperature, Tape and Reel
footprint MSOP-MS8_N (TSOP, 8-Leads, Body 3x3mm, Pitch 0.65mm, IPC Medium Density)
footprint MSOP-MS8_L (TSOP, 8-Leads, Body 3x3mm, Pitch 0.65mm, IPC High Density)
footprint MSOP-MS8_M (TSOP, 8-Leads, Body 3x3mm, Pitch 0.65mm, IPC Low Density)
pins: 1 ~{CS} (in), 2 SO (hiz), 3 ~{WP} (in), 4 VSS (power), 5 SI (in), 6 SCK (in), 7 ~{HOLD} (in), 8 VCC (power)

## 25AA080CT-I/SN
designator U?
8K SPI Bus Serial EEPROM, 8-Pin SOIC, Industrial Temperature, Tape and Reel
footprint SOIC-SN8_N (SOIC, 8-Leads, Body 4.9x3.8mm, Pitch 1.27mm, IPC Medium Density)
footprint SOIC-SN8_L (SOIC, 8-Leads, Body 4.9x3.8mm, Pitch 1.27mm, IPC High Density)
footprint SOIC-SN8_M (SOIC, 8-Leads, Body 4.9x3.8mm, Pitch 1.27mm, IPC Low Density)
pins: 1 ~{CS} (in), 2 SO (hiz), 3 ~{WP} (in), 4 VSS (power), 5 SI (in), 6 SCK (in), 7 ~{HOLD} (in), 8 VCC (power)

## 25AA080CT-I/ST
designator U?
8K SPI Bus Serial EEPROM, 8-Pin TSSOP, Industrial Temperature, Tape and Reel
footprint TSSOP-ST8_N (TSOP, 8-Leads, Body 3x4.4mm, Pitch 0.65mm, IPC Medium Density)
footprint TSSOP-ST8_L (TSOP, 8-Leads, Body 3x4.4mm, Pitch 0.65mm, IPC High Density)
footprint TSSOP-ST8_M (TSOP, 8-Leads, Body 3x4.4mm, Pitch 0.65mm, IPC Low Density)
pins: 1 ~{CS} (in), 2 SO (hiz), 3 ~{WP} (in), 4 VSS (power), 5 SI (in), 6 SCK (in), 7 ~{HOLD} (in), 8 VCC (power)

## 25AA080D-I/MNY
designator U?
8K SPI Bus Serial EEPROM, 8-Pin TDFN, Industrial Temperature
footprint TDFN-MN8 (SON, 8-Leads, Body 2x3mm, Pitch 0.5mm, Microchip Recommended)
pins: 1 ~{CS} (in), 2 SO (hiz), 3 ~{WP} (in), 4 VSS (power), 5 SI (in), 6 SCK (in), 7 ~{HOLD} (in), 8 VCC (power), 9 EP

## 25AA080D-I/MS
designator U?
8K SPI Bus Serial EEPROM, 8-Pin MSOP, Industrial Temperature
footprint MSOP-MS8_N (TSOP, 8-Leads, Body 3x3mm, Pitch 0.65mm, IPC Medium Density)
footprint MSOP-MS8_L (TSOP, 8-Leads, Body 3x3mm, Pitch 0.65mm, IPC High Density)
footprint MSOP-MS8_M (TSOP, 8-Leads, Body 3x3mm, Pitch 0.65mm, IPC Low Density)
pins: 1 ~{CS} (in), 2 SO (hiz), 3 ~{WP} (in), 4 VSS (power), 5 SI (in), 6 SCK (in), 7 ~{HOLD} (in), 8 VCC (power)

## 25AA080D-I/P
designator U?
8K SPI Bus Serial EEPROM, 8-Pin PDIP, Industrial Temperature
footprint PDIP300-P8 (DIP, 8-Leads, Row Spacing 7.62mm, Pitch 2.54mm, Body 9.5x6.6mm)
pins: 1 ~{CS} (in), 2 SO (hiz), 3 ~{WP} (in), 4 VSS (power), 5 SI (in), 6 SCK (in), 7 ~{HOLD} (in), 8 VCC (power)

## 25AA080D-I/SN
designator U?
8K SPI Bus Serial EEPROM, 8-Pin SOIC, Industrial Temperature
footprint SOIC-SN8_N (SOIC, 8-Leads, Body 4.9x3.8mm, Pitch 1.27mm, IPC Medium Density)
footprint SOIC-SN8_L (SOIC, 8-Leads, Body 4.9x3.8mm, Pitch 1.27mm, IPC High Density)
footprint SOIC-SN8_M (SOIC, 8-Leads, Body 4.9x3.8mm, Pitch 1.27mm, IPC Low Density)
pins: 1 ~{CS} (in), 2 SO (hiz), 3 ~{WP} (in), 4 VSS (power), 5 SI (in), 6 SCK (in), 7 ~{HOLD} (in), 8 VCC (power)

## 25AA080D-I/ST
designator U?
8K SPI Bus Serial EEPROM, 8-Pin TSSOP, Industrial Temperature
footprint TSSOP-ST8_N (TSOP, 8-Leads, Body 3x4.4mm, Pitch 0.65mm, IPC Medium Density)
footprint TSSOP-ST8_L (TSOP, 8-Leads, Body 3x4.4mm, Pitch 0.65mm, IPC High Density)
footprint TSSOP-ST8_M (TSOP, 8-Leads, Body 3x4.4mm, Pitch 0.65mm, IPC Low Density)
pins: 1 ~{CS} (in), 2 SO (hiz), 3 ~{WP} (in), 4 VSS (power), 5 SI (in), 6 SCK (in), 7 ~{HOLD} (in), 8 VCC (power)

## 25AA080DT-I/MNY
designator U?
8K SPI Bus Serial EEPROM, 8-Pin TDFN, Industrial Temperature, Tape and Reel
footprint TDFN-MN8 (SON, 8-Leads, Body 2x3mm, Pitch 0.5mm, Microchip Recommended)
pins: 1 ~{CS} (in), 2 SO (hiz), 3 ~{WP} (in), 4 VSS (power), 5 SI (in), 6 SCK (in), 7 ~{HOLD} (in), 8 VCC (power), 9 EP

## 25AA080DT-I/MS
designator U?
8K SPI Bus Serial EEPROM, 8-Pin MSOP, Industrial Temperature, Tape and Reel
footprint MSOP-MS8_N (TSOP, 8-Leads, Body 3x3mm, Pitch 0.65mm, IPC Medium Density)
footprint MSOP-MS8_L (TSOP, 8-Leads, Body 3x3mm, Pitch 0.65mm, IPC High Density)
footprint MSOP-MS8_M (TSOP, 8-Leads, Body 3x3mm, Pitch 0.65mm, IPC Low Density)
pins: 1 ~{CS} (in), 2 SO (hiz), 3 ~{WP} (in), 4 VSS (power), 5 SI (in), 6 SCK (in), 7 ~{HOLD} (in), 8 VCC (power)

## 25AA080DT-I/SN
designator U?
8K SPI Bus Serial EEPROM, 8-Pin SOIC, Industrial Temperature, Tape and Reel
footprint SOIC-SN8_N (SOIC, 8-Leads, Body 4.9x3.8mm, Pitch 1.27mm, IPC Medium Density)
footprint SOIC-SN8_L (SOIC, 8-Leads, Body 4.9x3.8mm, Pitch 1.27mm, IPC High Density)
footprint SOIC-SN8_M (SOIC, 8-Leads, Body 4.9x3.8mm, Pitch 1.27mm, IPC Low Density)
pins: 1 ~{CS} (in), 2 SO (hiz), 3 ~{WP} (in), 4 VSS (power), 5 SI (in), 6 SCK (in), 7 ~{HOLD} (in), 8 VCC (power)

## 25AA080DT-I/ST
designator U?
8K SPI Bus Serial EEPROM, 8-Pin TSSOP, Industrial Temperature, Tape and Reel
footprint TSSOP-ST8_N (TSOP, 8-Leads, Body 3x4.4mm, Pitch 0.65mm, IPC Medium Density)
footprint TSSOP-ST8_L (TSOP, 8-Leads, Body 3x4.4mm, Pitch 0.65mm, IPC High Density)
footprint TSSOP-ST8_M (TSOP, 8-Leads, Body 3x4.4mm, Pitch 0.65mm, IPC Low Density)
pins: 1 ~{CS} (in), 2 SO (hiz), 3 ~{WP} (in), 4 VSS (power), 5 SI (in), 6 SCK (in), 7 ~{HOLD} (in), 8 VCC (power)

## 25AA128-I/MF
designator U?
128K SPI Bus Serial EEPROM, 8-Pin DFN, Industrial Temperature
footprint DFNS-MF8_PS (SON, 8-Leads, Body 5x6mm, Pitch 1.27mm)
pins: 1 ~{CS} (in), 2 SO (hiz), 3 ~{WP} (in), 4 VSS (power), 5 SI (in), 6 SCK (in), 7 ~{HOLD} (in), 8 VCC (power), 9 EP

## 25AA128-I/P
designator U?
128K SPI Bus Serial EEPROM, 8-Pin PDIP, Industrial Temperature
footprint PDIP300-P8 (DIP, 8-Leads, Row Spacing 7.62mm, Pitch 2.54mm, Body 9.5x6.6mm)
pins: 1 ~{CS} (in), 2 SO (hiz), 3 ~{WP} (in), 4 VSS (power), 5 SI (in), 6 SCK (in), 7 ~{HOLD} (in), 8 VCC (power)

## 25AA128-I/SM
designator U?
128K SPI Bus Serial EEPROM, 8-Pin SOIJ, Industrial Temperature
footprint SOIJ-SM8_N (SOP, 8-Leads, Body 5.2x5.2mm, Pitch 1.27mm, IPC Medium Density)
footprint SOIJ-SM8_L (SOP, 8-Leads, Body 5.2x5.2mm, Pitch 1.27mm, IPC High Density)
footprint SOIJ-SM8_M (SOP, 8-Leads, Body 5.2x5.2mm, Pitch 1.27mm, IPC Low Density)
pins: 1 ~{CS} (in), 2 SO (hiz), 3 ~{WP} (in), 4 VSS (power), 5 SI (in), 6 SCK (in), 7 ~{HOLD} (in), 8 VCC (power)

## 25AA128-I/SN
designator U?
128K SPI Bus Serial EEPROM, 8-Pin SOIC, Industrial Temperature
footprint SOIC-SN8_N (SOIC, 8-Leads, Body 4.9x3.8mm, Pitch 1.27mm, IPC Medium Density)
footprint SOIC-SN8_L (SOIC, 8-Leads, Body 4.9x3.8mm, Pitch 1.27mm, IPC High Density)
footprint SOIC-SN8_M (SOIC, 8-Leads, Body 4.9x3.8mm, Pitch 1.27mm, IPC Low Density)
pins: 1 ~{CS} (in), 2 SO (hiz), 3 ~{WP} (in), 4 VSS (power), 5 SI (in), 6 SCK (in), 7 ~{HOLD} (in), 8 VCC (power)

## 25AA128-I/ST
designator U?
128K SPI Bus Serial EEPROM, 8-Pin TSSOP, Industrial Temperature
footprint TSSOP-ST8_N (TSOP, 8-Leads, Body 3x4.4mm, Pitch 0.65mm, IPC Medium Density)
footprint TSSOP-ST8_L (TSOP, 8-Leads, Body 3x4.4mm, Pitch 0.65mm, IPC High Density)
footprint TSSOP-ST8_M (TSOP, 8-Leads, Body 3x4.4mm, Pitch 0.65mm, IPC Low Density)
pins: 1 ~{CS} (in), 2 SO (hiz), 3 ~{WP} (in), 4 VSS (power), 5 SI (in), 6 SCK (in), 7 ~{HOLD} (in), 8 VCC (power)

## 25AA128T-I/MF
designator U?
128K SPI Bus Serial EEPROM, 8-Pin DFN, Industrial Temperature, Tape and Reel
footprint DFNS-MF8_PS (SON, 8-Leads, Body 5x6mm, Pitch 1.27mm)
pins: 1 ~{CS} (in), 2 SO (hiz), 3 ~{WP} (in), 4 VSS (power), 5 SI (in), 6 SCK (in), 7 ~{HOLD} (in), 8 VCC (power), 9 EP

## 25AA128T-I/SM
designator U?
128K SPI Bus Serial EEPROM, 8-Pin SOIJ, Industrial Temperature, Tape and Reel
footprint SOIJ-SM8_N (SOP, 8-Leads, Body 5.2x5.2mm, Pitch 1.27mm, IPC Medium Density)
footprint SOIJ-SM8_L (SOP, 8-Leads, Body 5.2x5.2mm, Pitch 1.27mm, IPC High Density)
footprint SOIJ-SM8_M (SOP, 8-Leads, Body 5.2x5.2mm, Pitch 1.27mm, IPC Low Density)
pins: 1 ~{CS} (in), 2 SO (hiz), 3 ~{WP} (in), 4 VSS (power), 5 SI (in), 6 SCK (in), 7 ~{HOLD} (in), 8 VCC (power)

## 25AA128T-I/SN
designator U?
128K SPI Bus Serial EEPROM, 8-Pin SOIC, Industrial Temperature, Tape and Reel
footprint SOIC-SN8_N (SOIC, 8-Leads, Body 4.9x3.8mm, Pitch 1.27mm, IPC Medium Density)
footprint SOIC-SN8_L (SOIC, 8-Leads, Body 4.9x3.8mm, Pitch 1.27mm, IPC High Density)
footprint SOIC-SN8_M (SOIC, 8-Leads, Body 4.9x3.8mm, Pitch 1.27mm, IPC Low Density)
pins: 1 ~{CS} (in), 2 SO (hiz), 3 ~{WP} (in), 4 VSS (power), 5 SI (in), 6 SCK (in), 7 ~{HOLD} (in), 8 VCC (power)

## 25AA128T-I/ST
designator U?
128K SPI Bus Serial EEPROM, 8-Pin TSSOP, Industrial Temperature, Tape and Reel
footprint TSSOP-ST8_N (TSOP, 8-Leads, Body 3x4.4mm, Pitch 0.65mm, IPC Medium Density)
footprint TSSOP-ST8_L (TSOP, 8-Leads, Body 3x4.4mm, Pitch 0.65mm, IPC High Density)
footprint TSSOP-ST8_M (TSOP, 8-Leads, Body 3x4.4mm, Pitch 0.65mm, IPC Low Density)
pins: 1 ~{CS} (in), 2 SO (hiz), 3 ~{WP} (in), 4 VSS (power), 5 SI (in), 6 SCK (in), 7 ~{HOLD} (in), 8 VCC (power)

## 25AA160A-I/MS
designator U?
16K SPI Bus Serial EEPROM, 8-Pin MSOP, Industrial Temperature; ComponentAvailability: Unknown. Contact manufacturer to determine status.
footprint MSOP-MS8_N (TSOP, 8-Leads, Body 3x3mm, Pitch 0.65mm, IPC Medium Density)
footprint MSOP-MS8_L (TSOP, 8-Leads, Body 3x3mm, Pitch 0.65mm, IPC High Density)
footprint MSOP-MS8_M (TSOP, 8-Leads, Body 3x3mm, Pitch 0.65mm, IPC Low Density)
pins: 1 ~{CS} (in), 2 SO (hiz), 3 ~{WP} (in), 4 VSS (power), 5 SI (in), 6 SCK (in), 7 ~{HOLD} (in), 8 VCC (power)

## 25AA160A-I/P
designator U?
16K SPI Bus Serial EEPROM, 8-Pin PDIP, Industrial Temperature; ComponentAvailability: Unknown. Contact manufacturer to determine status.
footprint PDIP300-P8 (DIP, 8-Leads, Row Spacing 7.62mm, Pitch 2.54mm, Body 9.5x6.6mm)
pins: 1 ~{CS} (in), 2 SO (hiz), 3 ~{WP} (in), 4 VSS (power), 5 SI (in), 6 SCK (in), 7 ~{HOLD} (in), 8 VCC (power)

## 25AA160A-I/SN
designator U?
16K SPI Bus Serial EEPROM, 8-Pin SOIC, Industrial Temperature; ComponentAvailability: Unknown. Contact manufacturer to determine status.
footprint SOIC-SN8_N (SOIC, 8-Leads, Body 4.9x3.8mm, Pitch 1.27mm, IPC Medium Density)
footprint SOIC-SN8_L (SOIC, 8-Leads, Body 4.9x3.8mm, Pitch 1.27mm, IPC High Density)
footprint SOIC-SN8_M (SOIC, 8-Leads, Body 4.9x3.8mm, Pitch 1.27mm, IPC Low Density)
pins: 1 ~{CS} (in), 2 SO (hiz), 3 ~{WP} (in), 4 VSS (power), 5 SI (in), 6 SCK (in), 7 ~{HOLD} (in), 8 VCC (power)

## 25AA160A-I/ST
designator U?
16K SPI Bus Serial EEPROM, 8-Pin TSSOP, Industrial Temperature; ComponentAvailability: Unknown. Contact manufacturer to determine status.
footprint TSSOP-ST8_N (TSOP, 8-Leads, Body 3x4.4mm, Pitch 0.65mm, IPC Medium Density)
footprint TSSOP-ST8_L (TSOP, 8-Leads, Body 3x4.4mm, Pitch 0.65mm, IPC High Density)
footprint TSSOP-ST8_M (TSOP, 8-Leads, Body 3x4.4mm, Pitch 0.65mm, IPC Low Density)
pins: 1 ~{CS} (in), 2 SO (hiz), 3 ~{WP} (in), 4 VSS (power), 5 SI (in), 6 SCK (in), 7 ~{HOLD} (in), 8 VCC (power)

## 25AA160AT-I/MS
designator U?
16K SPI Bus Serial EEPROM, 8-Pin MSOP, Industrial Temperature, Tape and Reel; ComponentAvailability: Unknown. Contact manufacturer to determine status.
footprint MSOP-MS8_N (TSOP, 8-Leads, Body 3x3mm, Pitch 0.65mm, IPC Medium Density)
footprint MSOP-MS8_L (TSOP, 8-Leads, Body 3x3mm, Pitch 0.65mm, IPC High Density)
footprint MSOP-MS8_M (TSOP, 8-Leads, Body 3x3mm, Pitch 0.65mm, IPC Low Density)
pins: 1 ~{CS} (in), 2 SO (hiz), 3 ~{WP} (in), 4 VSS (power), 5 SI (in), 6 SCK (in), 7 ~{HOLD} (in), 8 VCC (power)

## 25AA160AT-I/SN
designator U?
16K SPI Bus Serial EEPROM, 8-Pin SOIC, Industrial Temperature, Tape and Reel; ComponentAvailability: Unknown. Contact manufacturer to determine status.
footprint SOIC-SN8_N (SOIC, 8-Leads, Body 4.9x3.8mm, Pitch 1.27mm, IPC Medium Density)
footprint SOIC-SN8_L (SOIC, 8-Leads, Body 4.9x3.8mm, Pitch 1.27mm, IPC High Density)
footprint SOIC-SN8_M (SOIC, 8-Leads, Body 4.9x3.8mm, Pitch 1.27mm, IPC Low Density)
pins: 1 ~{CS} (in), 2 SO (hiz), 3 ~{WP} (in), 4 VSS (power), 5 SI (in), 6 SCK (in), 7 ~{HOLD} (in), 8 VCC (power)

## 25AA160AT-I/ST
designator U?
16K SPI Bus Serial EEPROM, 8-Pin TSSOP, Industrial Temperature, Tape and Reel; ComponentAvailability: Unknown. Contact manufacturer to determine status.
footprint TSSOP-ST8_N (TSOP, 8-Leads, Body 3x4.4mm, Pitch 0.65mm, IPC Medium Density)
footprint TSSOP-ST8_L (TSOP, 8-Leads, Body 3x4.4mm, Pitch 0.65mm, IPC High Density)
footprint TSSOP-ST8_M (TSOP, 8-Leads, Body 3x4.4mm, Pitch 0.65mm, IPC Low Density)
pins: 1 ~{CS} (in), 2 SO (hiz), 3 ~{WP} (in), 4 VSS (power), 5 SI (in), 6 SCK (in), 7 ~{HOLD} (in), 8 VCC (power)

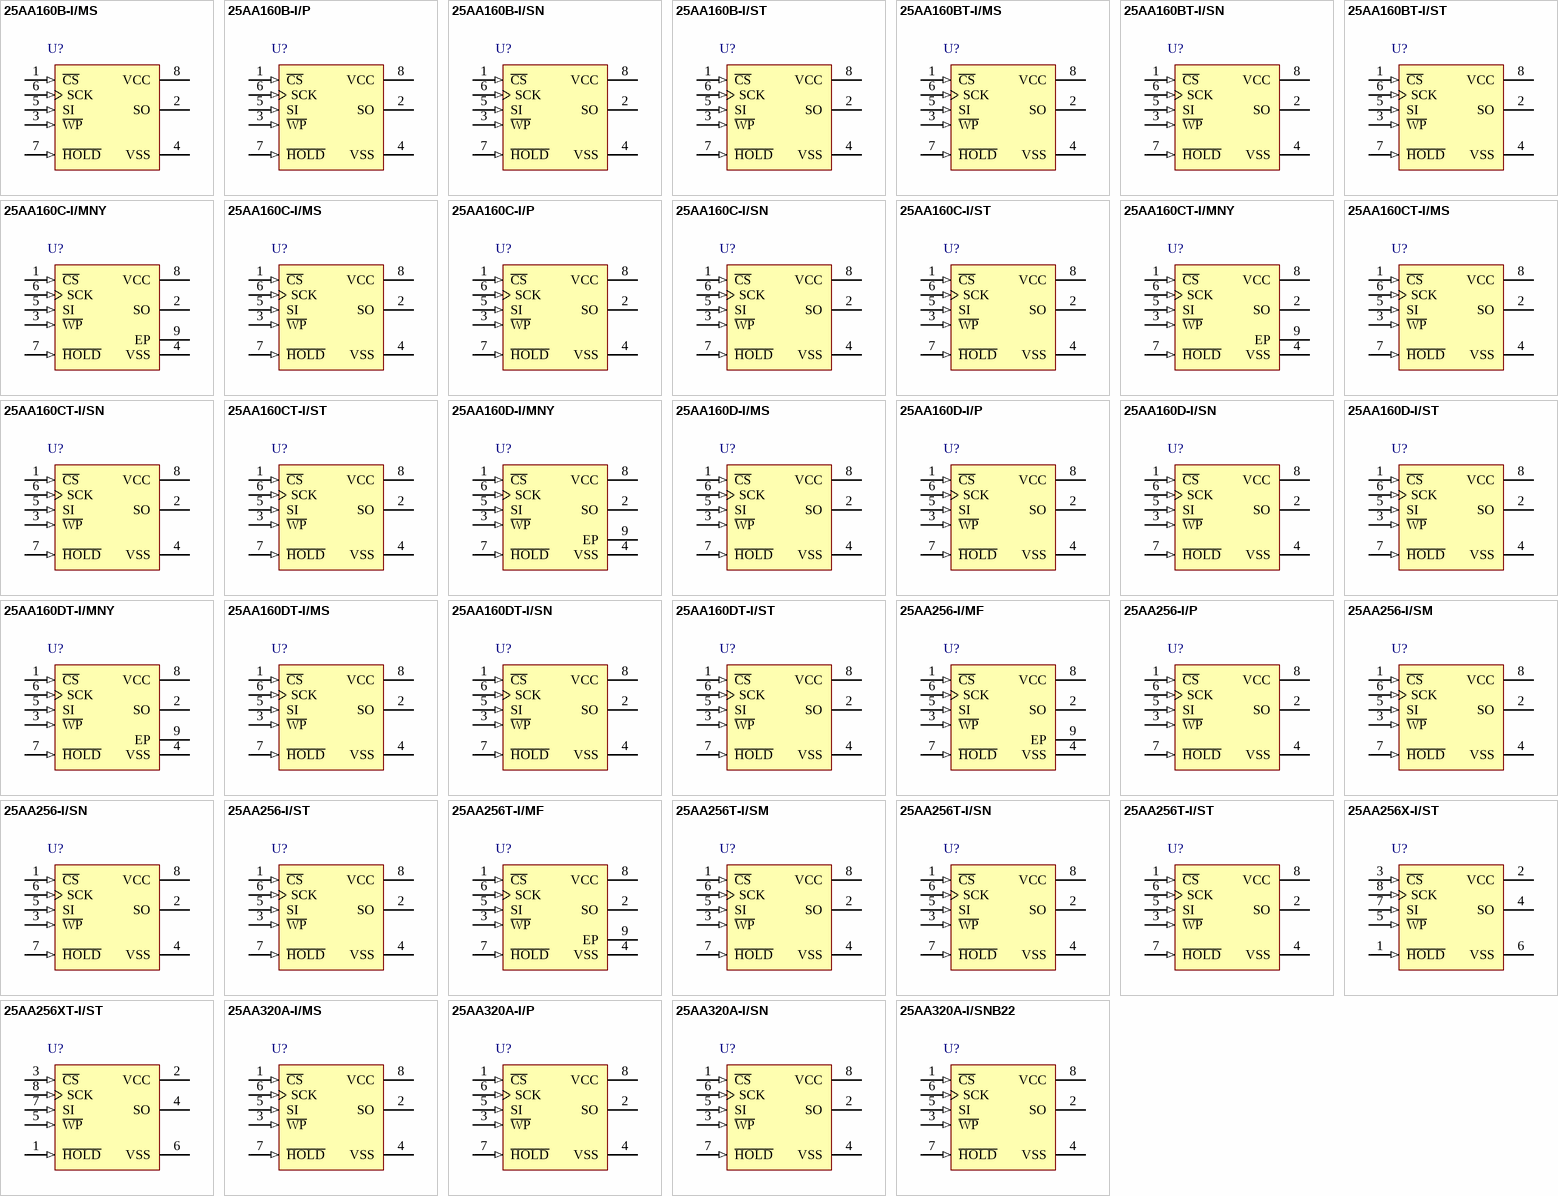
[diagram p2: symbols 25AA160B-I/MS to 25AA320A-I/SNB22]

## 25AA160B-I/MS
designator U?
16K SPI Bus Serial EEPROM, 8-Pin MSOP, Industrial Temperature; ComponentAvailability: Unknown. Contact manufacturer to determine status.
footprint MSOP-MS8_N (TSOP, 8-Leads, Body 3x3mm, Pitch 0.65mm, IPC Medium Density)
footprint MSOP-MS8_L (TSOP, 8-Leads, Body 3x3mm, Pitch 0.65mm, IPC High Density)
footprint MSOP-MS8_M (TSOP, 8-Leads, Body 3x3mm, Pitch 0.65mm, IPC Low Density)
pins: 1 ~{CS} (in), 2 SO (hiz), 3 ~{WP} (in), 4 VSS (power), 5 SI (in), 6 SCK (in), 7 ~{HOLD} (in), 8 VCC (power)

## 25AA160B-I/P
designator U?
16K SPI Bus Serial EEPROM, 8-Pin PDIP, Industrial Temperature; ComponentAvailability: Unknown. Contact manufacturer to determine status.
footprint PDIP300-P8 (DIP, 8-Leads, Row Spacing 7.62mm, Pitch 2.54mm, Body 9.5x6.6mm)
pins: 1 ~{CS} (in), 2 SO (hiz), 3 ~{WP} (in), 4 VSS (power), 5 SI (in), 6 SCK (in), 7 ~{HOLD} (in), 8 VCC (power)

## 25AA160B-I/SN
designator U?
16K SPI Bus Serial EEPROM, 8-Pin SOIC, Industrial Temperature; ComponentAvailability: Unknown. Contact manufacturer to determine status.
footprint SOIC-SN8_N (SOIC, 8-Leads, Body 4.9x3.8mm, Pitch 1.27mm, IPC Medium Density)
footprint SOIC-SN8_L (SOIC, 8-Leads, Body 4.9x3.8mm, Pitch 1.27mm, IPC High Density)
footprint SOIC-SN8_M (SOIC, 8-Leads, Body 4.9x3.8mm, Pitch 1.27mm, IPC Low Density)
pins: 1 ~{CS} (in), 2 SO (hiz), 3 ~{WP} (in), 4 VSS (power), 5 SI (in), 6 SCK (in), 7 ~{HOLD} (in), 8 VCC (power)

## 25AA160B-I/ST
designator U?
16K SPI Bus Serial EEPROM, 8-Pin TSSOP, Industrial Temperature; ComponentAvailability: Unknown. Contact manufacturer to determine status.
footprint TSSOP-ST8_N (TSOP, 8-Leads, Body 3x4.4mm, Pitch 0.65mm, IPC Medium Density)
footprint TSSOP-ST8_L (TSOP, 8-Leads, Body 3x4.4mm, Pitch 0.65mm, IPC High Density)
footprint TSSOP-ST8_M (TSOP, 8-Leads, Body 3x4.4mm, Pitch 0.65mm, IPC Low Density)
pins: 1 ~{CS} (in), 2 SO (hiz), 3 ~{WP} (in), 4 VSS (power), 5 SI (in), 6 SCK (in), 7 ~{HOLD} (in), 8 VCC (power)

## 25AA160BT-I/MS
designator U?
16K SPI Bus Serial EEPROM, 8-Pin MSOP, Industrial Temperature, Tape and Reel; ComponentAvailability: Unknown. Contact manufacturer to determine status.
footprint MSOP-MS8_N (TSOP, 8-Leads, Body 3x3mm, Pitch 0.65mm, IPC Medium Density)
footprint MSOP-MS8_L (TSOP, 8-Leads, Body 3x3mm, Pitch 0.65mm, IPC High Density)
footprint MSOP-MS8_M (TSOP, 8-Leads, Body 3x3mm, Pitch 0.65mm, IPC Low Density)
pins: 1 ~{CS} (in), 2 SO (hiz), 3 ~{WP} (in), 4 VSS (power), 5 SI (in), 6 SCK (in), 7 ~{HOLD} (in), 8 VCC (power)

## 25AA160BT-I/SN
designator U?
16K SPI Bus Serial EEPROM, 8-Pin SOIC, Industrial Temperature, Tape and Reel; ComponentAvailability: Unknown. Contact manufacturer to determine status.
footprint SOIC-SN8_N (SOIC, 8-Leads, Body 4.9x3.8mm, Pitch 1.27mm, IPC Medium Density)
footprint SOIC-SN8_L (SOIC, 8-Leads, Body 4.9x3.8mm, Pitch 1.27mm, IPC High Density)
footprint SOIC-SN8_M (SOIC, 8-Leads, Body 4.9x3.8mm, Pitch 1.27mm, IPC Low Density)
pins: 1 ~{CS} (in), 2 SO (hiz), 3 ~{WP} (in), 4 VSS (power), 5 SI (in), 6 SCK (in), 7 ~{HOLD} (in), 8 VCC (power)

## 25AA160BT-I/ST
designator U?
16K SPI Bus Serial EEPROM, 8-Pin TSSOP, Industrial Temperature, Tape and Reel; ComponentAvailability: Unknown. Contact manufacturer to determine status.
footprint TSSOP-ST8_N (TSOP, 8-Leads, Body 3x4.4mm, Pitch 0.65mm, IPC Medium Density)
footprint TSSOP-ST8_L (TSOP, 8-Leads, Body 3x4.4mm, Pitch 0.65mm, IPC High Density)
footprint TSSOP-ST8_M (TSOP, 8-Leads, Body 3x4.4mm, Pitch 0.65mm, IPC Low Density)
pins: 1 ~{CS} (in), 2 SO (hiz), 3 ~{WP} (in), 4 VSS (power), 5 SI (in), 6 SCK (in), 7 ~{HOLD} (in), 8 VCC (power)

## 25AA160C-I/MNY
designator U?
16K SPI Bus Serial EEPROM, 8-Pin TDFN, Industrial Temperature
footprint TDFN-MN8 (SON, 8-Leads, Body 2x3mm, Pitch 0.5mm, Microchip Recommended)
pins: 1 ~{CS} (in), 2 SO (hiz), 3 ~{WP} (in), 4 VSS (power), 5 SI (in), 6 SCK (in), 7 ~{HOLD} (in), 8 VCC (power), 9 EP

## 25AA160C-I/MS
designator U?
16K SPI Bus Serial EEPROM, 8-Pin MSOP, Industrial Temperature
footprint MSOP-MS8_N (TSOP, 8-Leads, Body 3x3mm, Pitch 0.65mm, IPC Medium Density)
footprint MSOP-MS8_L (TSOP, 8-Leads, Body 3x3mm, Pitch 0.65mm, IPC High Density)
footprint MSOP-MS8_M (TSOP, 8-Leads, Body 3x3mm, Pitch 0.65mm, IPC Low Density)
pins: 1 ~{CS} (in), 2 SO (hiz), 3 ~{WP} (in), 4 VSS (power), 5 SI (in), 6 SCK (in), 7 ~{HOLD} (in), 8 VCC (power)

## 25AA160C-I/P
designator U?
16K SPI Bus Serial EEPROM, 8-Pin PDIP, Industrial Temperature
footprint PDIP300-P8 (DIP, 8-Leads, Row Spacing 7.62mm, Pitch 2.54mm, Body 9.5x6.6mm)
pins: 1 ~{CS} (in), 2 SO (hiz), 3 ~{WP} (in), 4 VSS (power), 5 SI (in), 6 SCK (in), 7 ~{HOLD} (in), 8 VCC (power)

## 25AA160C-I/SN
designator U?
16K SPI Bus Serial EEPROM, 8-Pin SOIC, Industrial Temperature
footprint SOIC-SN8_N (SOIC, 8-Leads, Body 4.9x3.8mm, Pitch 1.27mm, IPC Medium Density)
footprint SOIC-SN8_L (SOIC, 8-Leads, Body 4.9x3.8mm, Pitch 1.27mm, IPC High Density)
footprint SOIC-SN8_M (SOIC, 8-Leads, Body 4.9x3.8mm, Pitch 1.27mm, IPC Low Density)
pins: 1 ~{CS} (in), 2 SO (hiz), 3 ~{WP} (in), 4 VSS (power), 5 SI (in), 6 SCK (in), 7 ~{HOLD} (in), 8 VCC (power)

## 25AA160C-I/ST
designator U?
16K SPI Bus Serial EEPROM, 8-Pin TSSO, Industrial Temperature
footprint TSSOP-ST8_N (TSOP, 8-Leads, Body 3x4.4mm, Pitch 0.65mm, IPC Medium Density)
footprint TSSOP-ST8_L (TSOP, 8-Leads, Body 3x4.4mm, Pitch 0.65mm, IPC High Density)
footprint TSSOP-ST8_M (TSOP, 8-Leads, Body 3x4.4mm, Pitch 0.65mm, IPC Low Density)
pins: 1 ~{CS} (in), 2 SO (hiz), 3 ~{WP} (in), 4 VSS (power), 5 SI (in), 6 SCK (in), 7 ~{HOLD} (in), 8 VCC (power)

## 25AA160CT-I/MNY
designator U?
16K SPI Bus Serial EEPROM, 8-Pin TDFN, Industrial Temperature, Tape and Reel
footprint TDFN-MN8 (SON, 8-Leads, Body 2x3mm, Pitch 0.5mm, Microchip Recommended)
pins: 1 ~{CS} (in), 2 SO (hiz), 3 ~{WP} (in), 4 VSS (power), 5 SI (in), 6 SCK (in), 7 ~{HOLD} (in), 8 VCC (power), 9 EP

## 25AA160CT-I/MS
designator U?
16K SPI Bus Serial EEPROM, 8-Pin MSOP, Industrial Temperature, Tape and Reel
footprint MSOP-MS8_N (TSOP, 8-Leads, Body 3x3mm, Pitch 0.65mm, IPC Medium Density)
footprint MSOP-MS8_L (TSOP, 8-Leads, Body 3x3mm, Pitch 0.65mm, IPC High Density)
footprint MSOP-MS8_M (TSOP, 8-Leads, Body 3x3mm, Pitch 0.65mm, IPC Low Density)
pins: 1 ~{CS} (in), 2 SO (hiz), 3 ~{WP} (in), 4 VSS (power), 5 SI (in), 6 SCK (in), 7 ~{HOLD} (in), 8 VCC (power)

## 25AA160CT-I/SN
designator U?
16K SPI Bus Serial EEPROM, 8-Pin SOIC, Industrial Temperature, Tape and Reel
footprint SOIC-SN8_N (SOIC, 8-Leads, Body 4.9x3.8mm, Pitch 1.27mm, IPC Medium Density)
footprint SOIC-SN8_L (SOIC, 8-Leads, Body 4.9x3.8mm, Pitch 1.27mm, IPC High Density)
footprint SOIC-SN8_M (SOIC, 8-Leads, Body 4.9x3.8mm, Pitch 1.27mm, IPC Low Density)
pins: 1 ~{CS} (in), 2 SO (hiz), 3 ~{WP} (in), 4 VSS (power), 5 SI (in), 6 SCK (in), 7 ~{HOLD} (in), 8 VCC (power)

## 25AA160CT-I/ST
designator U?
16K SPI Bus Serial EEPROM, 8-Pin TSSO, Industrial Temperature, Tape and Reel
footprint TSSOP-ST8_N (TSOP, 8-Leads, Body 3x4.4mm, Pitch 0.65mm, IPC Medium Density)
footprint TSSOP-ST8_L (TSOP, 8-Leads, Body 3x4.4mm, Pitch 0.65mm, IPC High Density)
footprint TSSOP-ST8_M (TSOP, 8-Leads, Body 3x4.4mm, Pitch 0.65mm, IPC Low Density)
pins: 1 ~{CS} (in), 2 SO (hiz), 3 ~{WP} (in), 4 VSS (power), 5 SI (in), 6 SCK (in), 7 ~{HOLD} (in), 8 VCC (power)

## 25AA160D-I/MNY
designator U?
16K SPI Bus Serial EEPROM, 8-Pin TDFN, Industrial Temperature
footprint TDFN-MN8 (SON, 8-Leads, Body 2x3mm, Pitch 0.5mm, Microchip Recommended)
pins: 1 ~{CS} (in), 2 SO (hiz), 3 ~{WP} (in), 4 VSS (power), 5 SI (in), 6 SCK (in), 7 ~{HOLD} (in), 8 VCC (power), 9 EP

## 25AA160D-I/MS
designator U?
16K SPI Bus Serial EEPROM, 8-Pin MSOP, Industrial Temperature
footprint MSOP-MS8_N (TSOP, 8-Leads, Body 3x3mm, Pitch 0.65mm, IPC Medium Density)
footprint MSOP-MS8_L (TSOP, 8-Leads, Body 3x3mm, Pitch 0.65mm, IPC High Density)
footprint MSOP-MS8_M (TSOP, 8-Leads, Body 3x3mm, Pitch 0.65mm, IPC Low Density)
pins: 1 ~{CS} (in), 2 SO (hiz), 3 ~{WP} (in), 4 VSS (power), 5 SI (in), 6 SCK (in), 7 ~{HOLD} (in), 8 VCC (power)

## 25AA160D-I/P
designator U?
16K SPI Bus Serial EEPROM, 8-Pin PDIP, Industrial Temperature
footprint PDIP300-P8 (DIP, 8-Leads, Row Spacing 7.62mm, Pitch 2.54mm, Body 9.5x6.6mm)
pins: 1 ~{CS} (in), 2 SO (hiz), 3 ~{WP} (in), 4 VSS (power), 5 SI (in), 6 SCK (in), 7 ~{HOLD} (in), 8 VCC (power)

## 25AA160D-I/SN
designator U?
16K SPI Bus Serial EEPROM, 8-Pin SOIC, Industrial Temperature
footprint SOIC-SN8_N (SOIC, 8-Leads, Body 4.9x3.8mm, Pitch 1.27mm, IPC Medium Density)
footprint SOIC-SN8_L (SOIC, 8-Leads, Body 4.9x3.8mm, Pitch 1.27mm, IPC High Density)
footprint SOIC-SN8_M (SOIC, 8-Leads, Body 4.9x3.8mm, Pitch 1.27mm, IPC Low Density)
pins: 1 ~{CS} (in), 2 SO (hiz), 3 ~{WP} (in), 4 VSS (power), 5 SI (in), 6 SCK (in), 7 ~{HOLD} (in), 8 VCC (power)

## 25AA160D-I/ST
designator U?
16K SPI Bus Serial EEPROM, 8-Pin TSSO, Industrial Temperature
footprint TSSOP-ST8_N (TSOP, 8-Leads, Body 3x4.4mm, Pitch 0.65mm, IPC Medium Density)
footprint TSSOP-ST8_L (TSOP, 8-Leads, Body 3x4.4mm, Pitch 0.65mm, IPC High Density)
footprint TSSOP-ST8_M (TSOP, 8-Leads, Body 3x4.4mm, Pitch 0.65mm, IPC Low Density)
pins: 1 ~{CS} (in), 2 SO (hiz), 3 ~{WP} (in), 4 VSS (power), 5 SI (in), 6 SCK (in), 7 ~{HOLD} (in), 8 VCC (power)

## 25AA160DT-I/MNY
designator U?
16K SPI Bus Serial EEPROM, 8-Pin TDFN, Industrial Temperature, Tape and Reel
footprint TDFN-MN8 (SON, 8-Leads, Body 2x3mm, Pitch 0.5mm, Microchip Recommended)
pins: 1 ~{CS} (in), 2 SO (hiz), 3 ~{WP} (in), 4 VSS (power), 5 SI (in), 6 SCK (in), 7 ~{HOLD} (in), 8 VCC (power), 9 EP

## 25AA160DT-I/MS
designator U?
16K SPI Bus Serial EEPROM, 8-Pin MSOP, Industrial Temperature, Tape and Reel
footprint MSOP-MS8_N (TSOP, 8-Leads, Body 3x3mm, Pitch 0.65mm, IPC Medium Density)
footprint MSOP-MS8_L (TSOP, 8-Leads, Body 3x3mm, Pitch 0.65mm, IPC High Density)
footprint MSOP-MS8_M (TSOP, 8-Leads, Body 3x3mm, Pitch 0.65mm, IPC Low Density)
pins: 1 ~{CS} (in), 2 SO (hiz), 3 ~{WP} (in), 4 VSS (power), 5 SI (in), 6 SCK (in), 7 ~{HOLD} (in), 8 VCC (power)

## 25AA160DT-I/SN
designator U?
16K SPI Bus Serial EEPROM, 8-Pin SOIC, Industrial Temperature, Tape and Reel
footprint SOIC-SN8_N (SOIC, 8-Leads, Body 4.9x3.8mm, Pitch 1.27mm, IPC Medium Density)
footprint SOIC-SN8_L (SOIC, 8-Leads, Body 4.9x3.8mm, Pitch 1.27mm, IPC High Density)
footprint SOIC-SN8_M (SOIC, 8-Leads, Body 4.9x3.8mm, Pitch 1.27mm, IPC Low Density)
pins: 1 ~{CS} (in), 2 SO (hiz), 3 ~{WP} (in), 4 VSS (power), 5 SI (in), 6 SCK (in), 7 ~{HOLD} (in), 8 VCC (power)

## 25AA160DT-I/ST
designator U?
16K SPI Bus Serial EEPROM, 8-Pin TSSO, Industrial Temperature, Tape and Reel
footprint TSSOP-ST8_N (TSOP, 8-Leads, Body 3x4.4mm, Pitch 0.65mm, IPC Medium Density)
footprint TSSOP-ST8_L (TSOP, 8-Leads, Body 3x4.4mm, Pitch 0.65mm, IPC High Density)
footprint TSSOP-ST8_M (TSOP, 8-Leads, Body 3x4.4mm, Pitch 0.65mm, IPC Low Density)
pins: 1 ~{CS} (in), 2 SO (hiz), 3 ~{WP} (in), 4 VSS (power), 5 SI (in), 6 SCK (in), 7 ~{HOLD} (in), 8 VCC (power)

## 25AA256-I/MF
designator U?
256K SPI Bus Serial EEPROM, 8-Pin DFN, Industrial Temperature
footprint DFNS-MF8_PS (SON, 8-Leads, Body 5x6mm, Pitch 1.27mm)
pins: 1 ~{CS} (in), 2 SO (hiz), 3 ~{WP} (in), 4 VSS (power), 5 SI (in), 6 SCK (in), 7 ~{HOLD} (in), 8 VCC (power), 9 EP

## 25AA256-I/P
designator U?
256K SPI Bus Serial EEPROM, 8-Pin PDIP, Industrial Temperature
footprint PDIP300-P8 (DIP, 8-Leads, Row Spacing 7.62mm, Pitch 2.54mm, Body 9.5x6.6mm)
pins: 1 ~{CS} (in), 2 SO (hiz), 3 ~{WP} (in), 4 VSS (power), 5 SI (in), 6 SCK (in), 7 ~{HOLD} (in), 8 VCC (power)

## 25AA256-I/SM
designator U?
256K SPI Bus Serial EEPROM, 8-Pin SOIC, Industrial Temperature
footprint SOIJ-SM8_N (SOP, 8-Leads, Body 5.2x5.2mm, Pitch 1.27mm, IPC Medium Density)
footprint SOIJ-SM8_L (SOP, 8-Leads, Body 5.2x5.2mm, Pitch 1.27mm, IPC High Density)
footprint SOIJ-SM8_M (SOP, 8-Leads, Body 5.2x5.2mm, Pitch 1.27mm, IPC Low Density)
pins: 1 ~{CS} (in), 2 SO (hiz), 3 ~{WP} (in), 4 VSS (power), 5 SI (in), 6 SCK (in), 7 ~{HOLD} (in), 8 VCC (power)

## 25AA256-I/SN
designator U?
256K SPI Bus Serial EEPROM, 8-Pin SOIC, Industrial Temperature
footprint SOIC-SN8_N (SOIC, 8-Leads, Body 4.9x3.8mm, Pitch 1.27mm, IPC Medium Density)
footprint SOIC-SN8_L (SOIC, 8-Leads, Body 4.9x3.8mm, Pitch 1.27mm, IPC High Density)
footprint SOIC-SN8_M (SOIC, 8-Leads, Body 4.9x3.8mm, Pitch 1.27mm, IPC Low Density)
pins: 1 ~{CS} (in), 2 SO (hiz), 3 ~{WP} (in), 4 VSS (power), 5 SI (in), 6 SCK (in), 7 ~{HOLD} (in), 8 VCC (power)

## 25AA256-I/ST
designator U?
256K SPI Bus Serial EEPROM, 8-Pin TSSOP, Industrial Temperature
footprint TSSOP-ST8_N (TSOP, 8-Leads, Body 3x4.4mm, Pitch 0.65mm, IPC Medium Density)
footprint TSSOP-ST8_L (TSOP, 8-Leads, Body 3x4.4mm, Pitch 0.65mm, IPC High Density)
footprint TSSOP-ST8_M (TSOP, 8-Leads, Body 3x4.4mm, Pitch 0.65mm, IPC Low Density)
pins: 1 ~{CS} (in), 2 SO (hiz), 3 ~{WP} (in), 4 VSS (power), 5 SI (in), 6 SCK (in), 7 ~{HOLD} (in), 8 VCC (power)

## 25AA256T-I/MF
designator U?
256K SPI Bus Serial EEPROM, 8-Pin DFN, Industrial Temperature, Tape and Reel
footprint DFNS-MF8_PS (SON, 8-Leads, Body 5x6mm, Pitch 1.27mm)
pins: 1 ~{CS} (in), 2 SO (hiz), 3 ~{WP} (in), 4 VSS (power), 5 SI (in), 6 SCK (in), 7 ~{HOLD} (in), 8 VCC (power), 9 EP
